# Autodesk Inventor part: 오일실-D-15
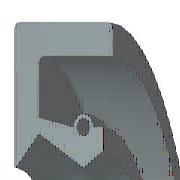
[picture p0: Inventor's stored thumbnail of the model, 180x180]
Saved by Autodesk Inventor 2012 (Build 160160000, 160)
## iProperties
IsCustomPart: 0
Company: 한국ATC센터
Created: 2014-12
Part Number: 오일실-D-15
Material: 고무
Description: 오일-실
Document SubType Name: Modeling
Standard: KS B 2804
Designer: KYOUNG IL JANG
Standards Organization: KS
Language: ko-KR
Size Designation: D - 15 30 7
Categories: <MemberInstance><Categories><Category DisplayName="샤프트 부품" InternalName="7f7aeb1f-a693-4053-b835-cee3144e0d98" Mnemonic="SHFT"><Category DisplayName="실링" Intern
Density: 0.93 g/cm^3
Mass: 1.95008 g
Surface Area: 27.8517 cm^2
Volume: 2.09686 cm^3
Author: KYOUNG IL JANG
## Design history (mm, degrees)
revolve "본체" stored, may be unused: angle "d17" = 90 deg
revolve "스프링1" stored, may be unused: angle "d18" = 90 deg
body "Solid1"
sketch "스케치1"
  geometry: L1 (0, 15)-(7, 15); L2 (7, 13.25)-(1.75, 13.25); L3 (1.75, 9.25)-(4.9, 7.5); L4 (4.9, 7.5)-(0, 7.5); L5 (0, 0)-(9.586, 0) reference; L6 (4.9, 7.5)-(6.3, 8.375); L7 (0, 18)-(0, -3) reference; L8 (-1.941, 0)-(11.507, 0) reference; L9 (4.2, 9.6)-(1.75, 10.09); L10 (1.75, 10.09)-(1.75, 13.25); L11 (0, 15)-(0, 7.588); L12 (4.9, 7.5)-(0, 7.5); L13 (1.75, 9.25)-(0.152, 7.528); L14 (7, 15)-(7, 13.25); L15 (5.6, 9.6)-(6.3, 9.6); L16 (6.3, 9.6)-(6.3, 8.375); C1 r 0.455 at (4.9, 9.6); A1 r 0.7 centre (4.9, 9.6) between (5.6, 9.6) and (4.2, 9.6); A2 r 0.088 centre (0.088, 7.588) between (0, 7.588) and (0.152, 7.528); 1 further point
  constraints: 28 end point, 5 horizontal alignment, 5 point on line, 4 point on circle, 4 vertical alignment, 3 centre point, 3 tangent, 2 collinear, 2 horizontal, 2 perpendicular, 1 coincident, 1 parallel
  dimensions: "d0" = 30 diameter of L1 L5 (= SD2); "d1" = 1.75 distance of L1.end L2.start (= SD); "d2" = 0.91 diameter of C1 (= SPDI); "d3" = 1.4 diameter of A1 (= SPDA); "d4" = 15 diameter of L3.end L5 (= NND); "d5" = 18.5 diameter of L3.start L5 (= TKDM); "d7" = 20.18 diameter of L9.end L5 (= TKDM + 0.24 x SWDT); "d8" = 1.75 distance between parallel lines of L11 L10 (= SD); "d9" = 4.9 distance from line of L11 C1.centre (= SPDST); "d10" = 19.2 diameter of C1.centre L5 (= HLDM); "d11" = 0.0875 radius of A2 (= 0.25 x LAB); "d12" = 6.3 distance between parallel lines of L11 L16 (= SDI); "d13" = 16.75 diameter of L6.end L5 (= ABDM); "d14" = 7 distance from line of L11 L1.end (= SWDT)
fillet "모깎기1" dims "d6" = 0.3 (= RR)
other parameters: "SD2" = 30 [user parameter; used in 1 equation term], "SWDT" = 7 [user parameter; used in 2 equation terms], "RR" = 0.3 [user parameter; used in 1 equation term], "SD" = 1.75 [user parameter; used in 2 equation terms], "NND" = 15 [user parameter; used in 1 equation term], "SPDA" = 1.4 [user parameter; used in 1 equation term], "SPDI" = 0.91 [user parameter; used in 1 equation term], "TKDM" = 18.5 [user parameter; used in 2 equation terms], "HLDM" = 19.2 [user parameter; used in 1 equation term], "ABDM" = 16.75 [user parameter; used in 1 equation term], "SDI" = 6.3 [user parameter; used in 1 equation term], "SPDST" = 4.9 [user parameter; used in 1 equation term], "LAB" = 0.35 [user parameter; used in 1 equation term], "d15" = 0, "d16" = 0, "d19" = 0
